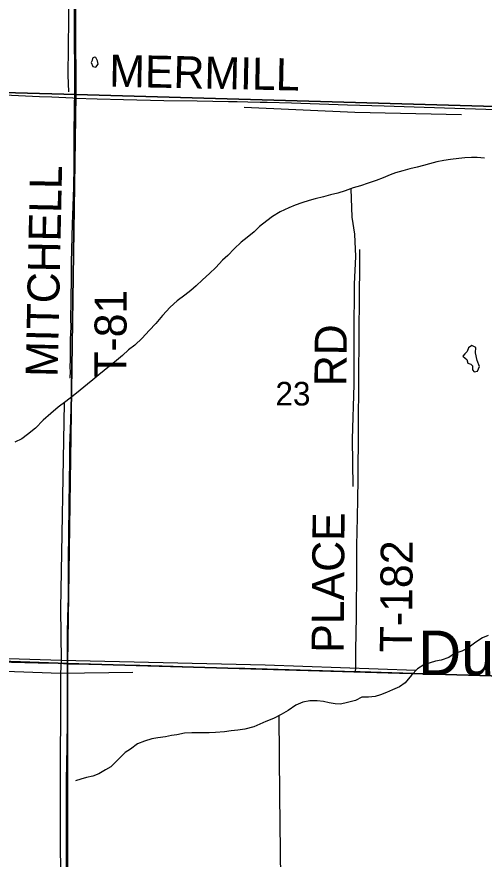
# Model space of a CAD drawing. Extents: x 0 to 39.4, y 0 to 22.
# Drawn here: x 3.277 to 4.106, y 17.096 to 18.59 of the extents above; entities that cross this region are included whole.
import ezdxf

# ---------------------------------------------------------------- set-up
doc = ezdxf.new("R2010")
doc.units = 0
for name, color, linetype in [('GM_X_County_Road', 7, 'Continuous'), ('GM_X_County_Road_Text', 7, 'Continuous'), ('GM_X_Major_River', 7, 'Continuous'), ('GM_X_Minor_Lake', 7, 'Continuous'), ('GM_X_Minor_River', 7, 'Continuous'), ('GM_X_Section', 7, 'Continuous'), ('GM_X_Section_Text', 7, 'Continuous'), ('GM_X_State_Route', 7, 'Continuous'), ('GM_X_Township_Road', 7, 'Continuous'), ('GM_X_Township_Road_Text', 7, 'Continuous'), ('GM_X_Unincorporated_Text', 7, 'Continuous')]:
    doc.layers.add(name, color=color, linetype=linetype)

msp = doc.modelspace()

# ---------------------------------------------------------------- linework, layer by layer
at = {"layer": 'GM_X_County_Road'}
for points in [[(2.8786, 18.4644), (2.9228, 18.4628), (2.9539, 18.462), (3.0098, 18.4606), (3.072, 18.4587), (3.1154, 18.4571), (3.1558, 18.4554), (3.1899, 18.4543), (3.2179, 18.4534), (3.2676, 18.4514), (3.3172, 18.4491), (3.339, 18.4481), (3.3762, 18.4463), (3.3797, 18.4462)], [(3.3797, 18.4462), (3.4197, 18.4448), (3.4663, 18.4434), (3.5378, 18.442), (3.5968, 18.4411), (3.6527, 18.4402), (3.6683, 18.4398), (3.6869, 18.4394), (3.7086, 18.439), (3.7117, 18.4389), (3.7211, 18.4386), (3.7646, 18.4375), (3.864, 18.4344), (3.9292, 18.4325), (3.982, 18.4306), (4.0721, 18.4275), (4.128, 18.4259), (4.1591, 18.4251), (4.187, 18.4246), (4.2119, 18.424), (4.2366, 18.4232), (4.2624, 18.4228)]]:
    msp.add_lwpolyline(points, dxfattribs=at)
at = {"layer": 'GM_X_Major_River'}
msp.add_lwpolyline([(4.1068, 18.3392), (4.0939, 18.3407), (4.0837, 18.3407), (4.0723, 18.34), (4.0613, 18.3389), (4.0465, 18.3371), (4.0347, 18.3356), (4.0222, 18.333), (4.0096, 18.3292), (3.999, 18.3262), (3.9876, 18.3236), (3.9747, 18.3206), (3.9622, 18.3168), (3.9493, 18.3134), (3.9398, 18.31), (3.9272, 18.3047), (3.9147, 18.2998), (3.9007, 18.2953), (3.887, 18.2904), (3.8737, 18.2867), (3.86, 18.2818), (3.8467, 18.2773), (3.8338, 18.2746), (3.8213, 18.2709), (3.8065, 18.2675), (3.7959, 18.2645), (3.7829, 18.26), (3.7708, 18.2558), (3.7598, 18.2513), (3.7442, 18.2445), (3.7305, 18.2362), (3.7206, 18.2283), (3.7077, 18.2184), (3.6982, 18.2089), (3.6856, 18.1987), (3.675, 18.1904), (3.6628, 18.1787), (3.6514, 18.1669), (3.6419, 18.1582), (3.6301, 18.1457), (3.6187, 18.1351), (3.6065, 18.1238), (3.5954, 18.1128), (3.5859, 18.1044), (3.5749, 18.0961), (3.5616, 18.0863), (3.5494, 18.0753), (3.5357, 18.0605), (3.5235, 18.0461), (3.5121, 18.0336), (3.4996, 18.02), (3.4866, 18.0079), (3.4752, 17.9992), (3.4646, 17.9893), (3.4539, 17.9806), (3.4414, 17.9704), (3.4319, 17.9625), (3.4223, 17.9553), (3.4117, 17.9462), (3.4022, 17.9386), (3.3896, 17.9276), (3.3771, 17.9178), (3.3638, 17.9076), (3.3501, 17.8977), (3.3375, 17.8864), (3.3238, 17.8743), (3.3101, 17.8606), (3.2957, 17.8489), (3.2858, 17.8417), (3.2736, 17.8353)], dxfattribs=at)
at = {"layer": 'GM_X_Minor_Lake'}
for p, q in [((3.4108, 18.5126), (3.4092, 18.5095)), ((4.0765, 17.9966), (4.072, 17.9924))]:
    msp.add_line(p, q, dxfattribs=at)
for points in [[(3.4092, 18.5095), (3.4119, 18.5023), (3.4172, 18.5011), (3.4214, 18.5061), (3.4199, 18.5125), (3.4172, 18.5179), (3.415, 18.5186), (3.4112, 18.5167), (3.4108, 18.5126)], [(4.072, 17.9924), (4.0685, 17.9883), (4.0727, 17.9845), (4.0757, 17.9822), (4.0776, 17.9757), (4.0829, 17.9738), (4.0856, 17.9707), (4.0859, 17.9639), (4.0889, 17.9601), (4.0946, 17.9616), (4.0981, 17.9699), (4.0939, 17.9802), (4.0909, 17.9939), (4.0914, 18.0034), (4.0842, 18.0068), (4.0788, 18.003), (4.0765, 17.9966)]]:
    msp.add_lwpolyline(points, dxfattribs=at)
at = {"layer": 'GM_X_Minor_River'}
for points in [[(3.3869, 19.3844), (3.3886, 19.3243), (3.3881, 19.2696), (3.3882, 19.1918), (3.3891, 19.123), (3.3698, 19.1216), (3.3686, 19.1117), (3.3678, 19.0973), (3.3681, 19.0825), (3.3702, 19.0012), (3.3696, 18.9313), (3.3694, 18.8872), (3.3685, 18.8356), (3.3706, 18.7653), (3.3699, 18.6722), (3.3689, 18.586), (3.3674, 18.4869), (3.3689, 18.4572)], [(3.6806, 18.4297), (3.8768, 18.4211), (4.0661, 18.4172)], [(3.8699, 18.2852), (3.8716, 18.2346), (3.8761, 18.2046), (3.8783, 18.1651), (3.8758, 18.1157), (3.8752, 18.0261), (3.8749, 17.9379), (3.8723, 17.8407), (3.8732, 17.7571)], [(3.3608, 17.9054), (3.3547, 17.5399), (3.3559, 17.4483), (3.3544, 17.4248), (3.3541, 17.2022), (3.3551, 16.7839), (3.3531, 16.5126), (3.3521, 16.4325)], [(4.1137, 17.4924), (4.1035, 17.4886), (4.0913, 17.4807), (4.0772, 17.4701), (4.0666, 17.4644), (4.0537, 17.4603), (4.0438, 17.4534), (4.0301, 17.4485), (4.0199, 17.4467), (4.0104, 17.444), (3.9994, 17.4403), (3.9879, 17.4335), (3.9773, 17.4221), (3.9659, 17.4085), (3.9564, 17.4013), (3.9438, 17.396), (3.9332, 17.3911), (3.9226, 17.3873), (3.9131, 17.3843), (3.9009, 17.3832), (3.8895, 17.3829), (3.8778, 17.3772), (3.8641, 17.3734), (3.8512, 17.3708), (3.8417, 17.3709), (3.8311, 17.3732), (3.8212, 17.3755), (3.8102, 17.3763), (3.7969, 17.3767), (3.7848, 17.3741), (3.7719, 17.3688), (3.7586, 17.3593), (3.7464, 17.3522), (3.7324, 17.3454), (3.7191, 17.3401), (3.6978, 17.3303), (3.6815, 17.3261), (3.6693, 17.3243), (3.6572, 17.3232), (3.6458, 17.3217), (3.6295, 17.3206), (3.6185, 17.3199), (3.6082, 17.3199), (3.5968, 17.3196), (3.5874, 17.32), (3.5745, 17.3189), (3.5612, 17.3162), (3.5517, 17.3148), (3.541, 17.3129), (3.5274, 17.311), (3.5164, 17.3088), (3.5038, 17.305), (3.4913, 17.3005), (3.4788, 17.291), (3.4693, 17.2846), (3.4552, 17.2706), (3.4438, 17.2596), (3.4343, 17.254), (3.4225, 17.2468), (3.4122, 17.2426), (3.4008, 17.2404), (3.3906, 17.2374), (3.3811, 17.2347)], [(3.9851, 17.4305), (3.7178, 17.44), (3.3559, 17.4483), (3.1503, 17.4543), (3.1097, 17.4555)], [(3.4826, 17.427), (3.3544, 17.4248), (3.1905, 17.431)], [(3.7422, 17.3501), (3.7429, 17.2086), (3.7464, 16.962), (3.7436, 16.8051)]]:
    msp.add_lwpolyline(points, dxfattribs=at)
at = {"layer": 'GM_X_Section'}
for points in [[(2.3842, 19.4785), (2.7709, 19.4617), (3.377, 19.4549), (3.3817, 18.4522), (2.3742, 18.4805)], [(3.377, 19.4549), (4.394, 19.4215), (4.3942, 18.4237), (3.3817, 18.4522)], [(2.3742, 18.4805), (3.3817, 18.4522), (3.367, 17.4429), (2.3633, 17.4784)], [(3.3817, 18.4522), (4.3942, 18.4237), (4.3832, 17.4133), (3.367, 17.4429)], [(2.3633, 17.4784), (3.367, 17.4429), (3.3671, 16.4448), (2.3619, 16.4807)], [(3.367, 17.4429), (4.3832, 17.4133), (4.3694, 16.4169), (3.3671, 16.4448)]]:
    msp.add_lwpolyline(points, close=True, dxfattribs=at)
at = {"layer": 'GM_X_State_Route'}
msp.add_lwpolyline([(3.2435, 17.446), (3.315, 17.4441), (3.3523, 17.4431), (3.3669, 17.4424), (3.374, 17.4422), (3.405, 17.4417), (3.4952, 17.4396), (3.5542, 17.4378), (3.6039, 17.4365), (3.6474, 17.4352), (3.6816, 17.4345), (3.7406, 17.4325), (3.8783, 17.4286), (3.8866, 17.4284), (3.9425, 17.4267), (4.0016, 17.4249), (4.0606, 17.4228), (4.1351, 17.4206)], dxfattribs=at)
at = {"layer": 'GM_X_Township_Road'}
for points in [[(3.3797, 18.4462), (3.3797, 18.5188), (3.3796, 18.5281), (3.3793, 18.5461), (3.3791, 18.5704), (3.3791, 18.6052)], [(3.3715, 17.949), (3.372, 17.9614), (3.3719, 17.9676), (3.3723, 17.9832), (3.3725, 18.0174), (3.3728, 18.0299), (3.3734, 18.0392), (3.3734, 18.0423), (3.3729, 18.0516), (3.374, 18.1263), (3.3741, 18.1543), (3.3757, 18.2228), (3.3763, 18.2383), (3.3781, 18.2881), (3.3789, 18.3255), (3.3789, 18.341), (3.3789, 18.3597), (3.3788, 18.3908), (3.3791, 18.4188), (3.3796, 18.4398), (3.3797, 18.4462)], [(3.8813, 17.7039), (3.882, 17.7329), (3.8825, 17.7702), (3.8834, 17.8573), (3.884, 17.9506), (3.8844, 18.0221), (3.8854, 18.0999), (3.8856, 18.1434), (3.8856, 18.1776)], [(3.3669, 17.4424), (3.367, 17.4968), (3.3676, 17.5248), (3.3685, 17.559), (3.369, 17.6274), (3.37, 17.7206), (3.3705, 17.7673), (3.3712, 17.8015), (3.3713, 17.8294), (3.3721, 17.8574), (3.3737, 17.8947)], [(3.8783, 17.4286), (3.8784, 17.435), (3.8789, 17.4659), (3.8794, 17.497), (3.8796, 17.525), (3.8796, 17.5343), (3.8798, 17.5529), (3.8803, 17.5871), (3.8807, 17.6337), (3.8807, 17.646), (3.8807, 17.6521), (3.8813, 17.7019), (3.8813, 17.7039)], [(3.3636, 16.4419), (3.3636, 16.4491), (3.3634, 16.4833), (3.3634, 16.5299), (3.3633, 16.5952), (3.364, 16.6543), (3.3647, 16.7724), (3.365, 16.8408), (3.3651, 17.0398), (3.365, 17.13), (3.365, 17.1953), (3.3654, 17.2357), (3.3663, 17.2948), (3.3667, 17.3414), (3.3668, 17.416), (3.3669, 17.4424)]]:
    msp.add_lwpolyline(points, dxfattribs=at)

# ---------------------------------------------------------------- texts
at = {"layer": 'GM_X_County_Road_Text'}
msp.add_text('MERMILL', height=0.05682, rotation=358.8186, dxfattribs=at).set_placement((3.4406, 18.4664))
at = {"layer": 'GM_X_Section_Text'}
msp.add_text('23', height=0.04186, rotation=0, dxfattribs=at).set_placement((3.7359, 17.9006))
at = {"layer": 'GM_X_Township_Road_Text'}
for s, rotation, p in [('MITCHELL', 88.7743, (3.3494, 17.9507)), ('T-81', 89.6542, (3.4712, 17.9497)), ('RD', 89.5125, (3.8619, 17.9346)), ('PLACE', 89.5696, (3.8569, 17.4616)), ('T-182', 89.4443, (3.9779, 17.4624))]:
    msp.add_text(s, height=0.05682, rotation=rotation, dxfattribs=at).set_placement(p)
at = {"layer": 'GM_X_Unincorporated_Text'}
msp.add_text('Ducat', height=0.07898, rotation=0, dxfattribs=at).set_placement((3.9893, 17.4222))

doc.saveas('drawing.dxf')
